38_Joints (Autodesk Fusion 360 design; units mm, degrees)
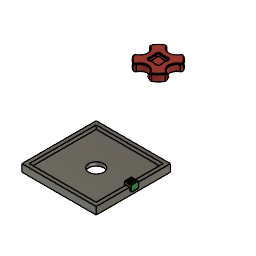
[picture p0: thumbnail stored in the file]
part number: 2026-07-20-09-11-35-992
part number: 2026-07-20-09-14-28-233
part number: 2026-07-20-09-17-14-408
part number: 2026-07-20-09-20-04-359
sketch "Sketch1" plane through (0, 0, 0) normal (0, 0, 1) x axis (1, 0, 0)
  line L1 (-50, -50) -> (50, -50)
  line L2 (-50, 50) -> (-50, -50)
  line L3 (50, 50) -> (-50, 50)
  line L4 (50, -50) -> (50, 50)
  line L5 (-50, 50) -> (50, -50)
  line L6 (50, 50) -> (-50, -50)
  point P6 (0, 0)
  point P1 (0, 0)
  point P4 (-50, 50)
  point P5 (50, 50)
  point P3 (-50, -50)
  horizontal L1
  perpendicular L1 L2
  parallel L1 L3
  parallel L2 L4
  coincident L5 P6
  coincident L6 P6
  coincident P1 P6
  dimension "d1" distance P4 P5 = 100
  dimension "d2" distance P3 P4 = 100
extrude "Extrude1" new body sketch "Sketch1" profile of L1 L2 L3 L4 along normal blind 10
shell "Shell1" innerThickness 5
sketch "Sketch2" plane through (0, 0, 5) normal (0, 0, 1) x axis (-1, 0, 0)
  line L1 (45, -45) -> (-45, -45)
  line L2 (45, 45) -> (45, -45)
  line L3 (-45, 45) -> (45, 45)
  line L4 (-45, -45) -> (-45, 45)
  circle C1 centre (0, 0) radius 10
  point P1 (0, 0)
  point P6 (0, 0)
  coincident P1 P6
  dimension "d6" diameter C1 = 20
extrude "Extrude2" cut sketch "Sketch2" profile of C1 no distance stored
sketch "Sketch1" plane through (0, 0, 0) normal (0, 1, 0) x axis (1, 0, 0)
  line L1 (50, 0) -> (50, -10)
  line L2 (10, 0) -> (50, 0)
  line L3 (10, -5) -> (10, 0)
  line L4 (45, -5) -> (10, -5)
  line L5 (45, -10) -> (45, -5)
  line L6 (50, -10) -> (45, -10)
  line L7 (-50, -10) -> (-50, 0)
  line L8 (-45, -10) -> (-50, -10)
  line L9 (-45, -5) -> (-45, -10)
  line L10 (-10, -5) -> (-45, -5)
  line L11 (-10, 0) -> (-10, -5)
  line L12 (-50, 0) -> (-10, 0)
  line L13 (43, -5) -> (45, -5)
  line L14 (43, -14) -> (43, -5)
  line L15 (52, -14) -> (43, -14)
  line L16 (52, -5) -> (52, -14)
  line L17 (50, -5) -> (52, -5)
  point P6 (45, -5)
  point P14 (45, -5)
  point P15 (43, -5)
  point P19 (50, -5)
  point P18 (52, -5)
  coincident P6 P14
  coincident L4 P15
  perpendicular L13 L14
  perpendicular L14 L15
  perpendicular L15 L16
  midpoint L1 P19
  perpendicular L1 L17
  equal L13 L17
  dimension "d12" distance P18 P19 = 2
  dimension "d13" distance L6 L15 = 4
extrude "Extrude1" new body sketch "Sketch1" profile of L1 L4 L5 L6 L13 L14 L15 L16 L17 distance 10
sketch "Sketch2" plane through (52, 0, 0) normal (1, 0, 0) x axis (0, 1, 0)
  line L1 (5, 5) -> (-5, 5)
  line L2 (5, 14) -> (5, 5)
  line L3 (-5, 14) -> (5, 14)
  line L4 (-5, 5) -> (-5, 14)
  circle C1 centre (-5, 14) radius 1
  point P5 (-5, 14)
  point P6 (-5, 14)
  coincident P5 P6
  dimension "d16" diameter C1 = 2
extrude "Extrude2" cut sketch "Sketch2" profile of L3 L4 C1 no distance stored
rectangular_pattern "R-Pattern1" uSpaceDistance 10 vSpaceDistance 0
chamfer "Chamfer1" distance 1
sketch "Sketch1" plane through (0, 0, 0) normal (1, 0, 0) x axis (0, 1, 0)
  line L1 (0, 20) -> (0, 0)
  line L2 (25, 20) -> (0, 20)
  line L3 (25, 10) -> (25, 20)
  line L4 (10, 10) -> (25, 10)
  line L5 (10, 0) -> (10, 10)
  line L6 (0, 0) -> (10, 0)
  point P1 (0, 0)
  point P2 (0, 0)
  point P3 (0, 20)
  point P6 (10, 10)
  point P7 (10, 0)
  coincident P1 P2
  vertical L1
  perpendicular L1 L2
  perpendicular L2 L3
  perpendicular L3 L4
  perpendicular L4 L5
  perpendicular L1 L6
  dimension "d23" = 20
  dimension "d24" distance P2 P3 = 20
  dimension "d25" = 50
  dimension "d26" distance P6 P7 = 10
revolve "Revolve1" sketch "Sketch1" AlongAngle 360
sketch "Sketch2" plane through (0, 0, 20) normal (0, 0, 1) x axis (-1, 0, 0)
  circle C1 centre (0, 0) radius 25
  circle C2 centre (0, -25) radius 10
  point P3 (0, -25)
  point P1 (0, 0)
  coincident C1 P3
  vertical P1 P3
  dimension "d28" diameter C2 = 20
extrude "Extrude1" cut sketch "Sketch2" no distance stored
circular_pattern "C-Pattern1" TotalAngle 360
fillet "Fillet1" radius 2.5
sketch "Sketch3" plane through (0, 0, 20) normal (0, 0, 1) x axis (-1, 0, 0)
  arc A1 centre (11.225, -19.5) radius 2.5 clockwise from (12.4722, -21.6667) to (8.98, -20.6)
  arc A2 centre (0, 0) radius 25 clockwise from (21.6667, -12.4722) to (12.4722, -21.6667)
  arc A3 centre (19.5, -11.225) radius 2.5 clockwise from (20.6, -8.98) to (21.6667, -12.4722)
  arc A4 centre (25, 0) radius 10 clockwise from (20.6, -8.98) to (20.6, 8.98)
  arc A5 centre (19.5, 11.225) radius 2.5 clockwise from (21.6667, 12.4722) to (20.6, 8.98)
  arc A6 centre (0, 0) radius 25 clockwise from (12.4722, 21.6667) to (21.6667, 12.4722)
  arc A7 centre (11.225, 19.5) radius 2.5 clockwise from (8.98, 20.6) to (12.4722, 21.6667)
  arc A8 centre (0, 25) radius 10 clockwise from (8.98, 20.6) to (-8.98, 20.6)
  arc A9 centre (-11.225, 19.5) radius 2.5 clockwise from (-12.4722, 21.6667) to (-8.98, 20.6)
  arc A10 centre (0, 0) radius 25 clockwise from (-21.6667, 12.4722) to (-12.4722, 21.6667)
  arc A11 centre (-19.5, 11.225) radius 2.5 clockwise from (-20.6, 8.98) to (-21.6667, 12.4722)
  arc A12 centre (-25, 0) radius 10 clockwise from (-20.6, 8.98) to (-20.6, -8.98)
  arc A13 centre (-19.5, -11.225) radius 2.5 clockwise from (-21.6667, -12.4722) to (-20.6, -8.98)
  arc A14 centre (0, 0) radius 25 clockwise from (-12.4722, -21.6667) to (-21.6667, -12.4722)
  arc A15 centre (-11.225, -19.5) radius 2.5 clockwise from (-8.98, -20.6) to (-12.4722, -21.6667)
  arc A16 centre (0, -25) radius 10 clockwise from (-8.98, -20.6) to (8.98, -20.6)
  arc A17 centre (0, 25) radius 18.3459 clockwise from (9.0306, 9.0306) to (-9.0306, 9.0306)
  arc A18 centre (-25, 0) radius 18.3459 clockwise from (-9.0306, 9.0306) to (-9.0306, -9.0306)
  arc A19 centre (0, -25) radius 18.3459 clockwise from (-9.0306, -9.0306) to (9.0306, -9.0306)
  arc A20 centre (25, 0) radius 18.3459 clockwise from (9.0306, -9.0306) to (9.0306, 9.0306)
  dimension "d34" = 8.3459
extrude "Extrude2" cut sketch "Sketch3" profile of A17 A20 A18 A19 against normal blind 4
fillet "Fillet2" radius 2
chamfer "Chamfer1" sketch "Sketch2" distance 1
position "Position1"
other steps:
create_component "CreateComponent1"
create_component "CreateComponent2"
create_component "CreateComponent3"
